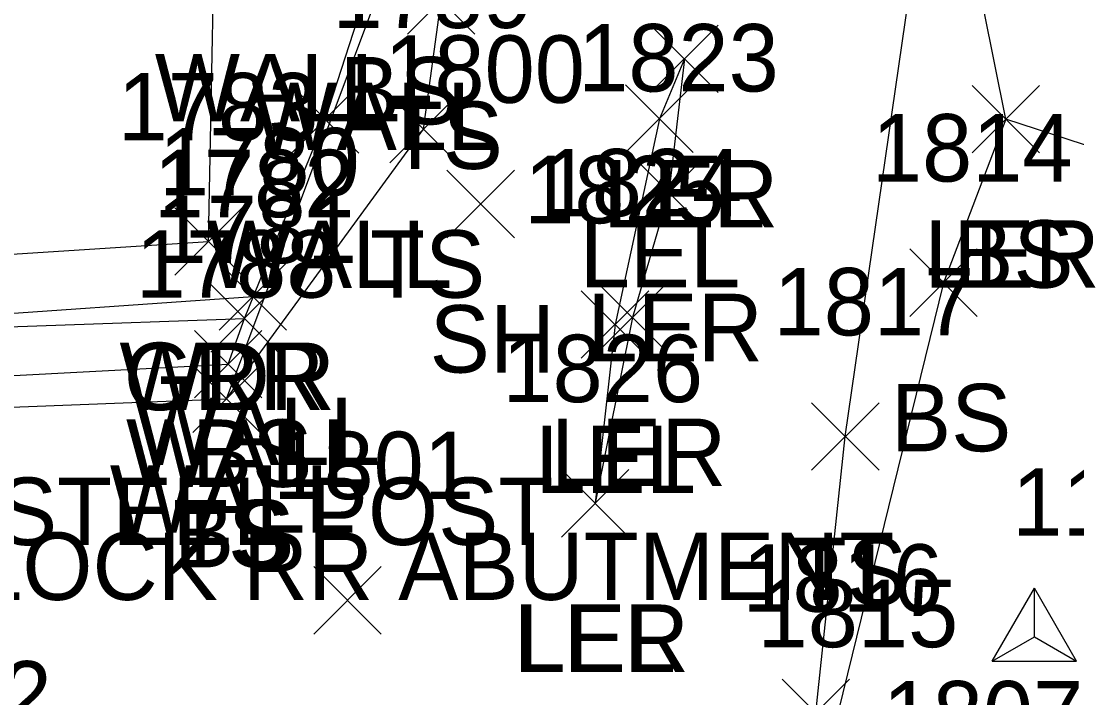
# Model space of a CAD drawing. Extents: x 1638344 to 1639591, y 610835 to 612202.
# Drawn here: x 1638637.19 to 1638668.48, y 611653.56 to 611673.63 of the extents above; entities that cross this region are included whole.
import ezdxf

# ---------------------------------------------------------------- set-up
doc = ezdxf.new("R2010")
doc.units = 0
for name, color, linetype in [('C_I', 7, 'Continuous'), ('CPSM', 7, 'Continuous'), ('L_A', 7, 'Continuous'), ('L_C', 7, 'Continuous'), ('L_I', 7, 'Continuous'), ('L_TIC', 7, 'Continuous'), ('LARO', 7, 'Continuous'), ('LAWA', 7, 'Continuous'), ('LELB', 7, 'Continuous'), ('LW', 7, 'Continuous'), ('R_A', 7, 'Continuous'), ('R_C', 7, 'Continuous'), ('R_I', 7, 'Continuous'), ('R_TIC', 7, 'Continuous'), ('RGR', 7, 'Continuous')]:
    doc.layers.add(name, color=color, linetype=linetype)

msp = doc.modelspace()

# ---------------------------------------------------------------- linework, layer by layer
at = {"layer": 'CPSM'}
for p, q in [((1638665.976, 611654.641), (1638667.226, 611656.806)), ((1638668.476, 611654.641), (1638667.226, 611656.806)), ((1638667.226, 611655.363), (1638667.226, 611656.806)), ((1638665.976, 611654.641), (1638667.226, 611655.363)), ((1638667.226, 611655.363), (1638667.226, 611655.363)), ((1638667.226, 611655.363), (1638668.476, 611654.641)), ((1638665.976, 611654.641), (1638668.476, 611654.641))]:
    msp.add_line(p, q, dxfattribs=at)
at = {"layer": 'L_TIC'}
for points in [[(1638648.64, 611673.242), (1638650.64, 611675.242)], [(1638650.64, 611673.242), (1638648.64, 611675.242)], [(1638655.848, 611671.507), (1638657.848, 611673.507)], [(1638657.848, 611671.507), (1638655.848, 611673.507)], [(1638655.848, 611671.507), (1638657.848, 611673.507)], [(1638657.848, 611671.507), (1638655.848, 611673.507)], [(1638655.107, 611669.733), (1638657.107, 611671.733)], [(1638657.107, 611669.733), (1638655.107, 611671.733)], [(1638665.378, 611669.719), (1638667.378, 611671.719)], [(1638667.378, 611669.719), (1638665.378, 611671.719)], [(1638665.378, 611669.719), (1638667.378, 611671.719)], [(1638667.378, 611669.719), (1638665.378, 611671.719)], [(1638645.203, 611669.713), (1638647.203, 611671.713)], [(1638647.203, 611669.713), (1638645.203, 611671.713)], [(1638648.116, 611669.423), (1638650.116, 611671.423)], [(1638650.116, 611669.423), (1638648.116, 611671.423)], [(1638655.391, 611667.54), (1638657.391, 611669.54)], [(1638657.391, 611667.54), (1638655.391, 611669.54)], [(1638649.809, 611667.203), (1638651.809, 611669.203)], [(1638651.809, 611667.203), (1638649.809, 611669.203)], [(1638641.742, 611666.089), (1638643.742, 611668.089)], [(1638643.742, 611666.089), (1638641.742, 611668.089)], [(1638663.532, 611664.869), (1638665.532, 611666.869)], [(1638665.532, 611664.869), (1638663.532, 611666.869)], [(1638643.053, 611664.46), (1638645.053, 611666.46)], [(1638645.053, 611664.46), (1638643.053, 611666.46)], [(1638642.81, 611663.812), (1638644.81, 611665.812)], [(1638644.81, 611663.812), (1638642.81, 611665.812)], [(1638642.81, 611663.812), (1638644.81, 611665.812)], [(1638644.81, 611663.812), (1638642.81, 611665.812)], [(1638654.307, 611663.835), (1638656.307, 611665.835)], [(1638656.307, 611663.835), (1638654.307, 611665.835)], [(1638653.792, 611663.632), (1638655.792, 611665.632)], [(1638655.792, 611663.632), (1638653.792, 611665.632)], [(1638642.327, 611662.451), (1638644.327, 611664.451)], [(1638644.327, 611662.451), (1638642.327, 611664.451)], [(1638642.277, 611661.426), (1638644.277, 611663.426)], [(1638644.277, 611661.426), (1638642.277, 611663.426)], [(1638642.277, 611661.426), (1638644.277, 611663.426)], [(1638644.277, 611661.426), (1638642.277, 611663.426)], [(1638660.619, 611660.306), (1638662.619, 611662.306)], [(1638662.619, 611660.306), (1638660.619, 611662.306)], [(1638653.201, 611658.326), (1638655.201, 611660.326)], [(1638655.201, 611658.326), (1638653.201, 611660.326)], [(1638653.201, 611658.326), (1638655.201, 611660.326)], [(1638655.201, 611658.326), (1638653.201, 611660.326)], [(1638645.864, 611655.45), (1638647.864, 611657.45)], [(1638647.864, 611655.45), (1638645.864, 611657.45)], [(1638659.747, 611652.111), (1638661.747, 611654.111)], [(1638661.747, 611652.111), (1638659.747, 611654.111)]]:
    msp.add_lwpolyline(points, dxfattribs=at)
at = {"layer": 'LARO'}
for points in [[(1638677.874, 611655.022), (1638679.486, 611663.994), (1638679.763, 611666.345), (1638666.378, 611670.719), (1638664.402, 611680.56), (1638659.089, 611680.603), (1638655.538, 611679.933), (1638651.379, 611684.077), (1638658.688, 611689.813), (1638660.426, 611695.236), (1638662.023, 611697.78), (1638662.102, 611697.781), (1638663.175, 611700.857), (1638663.547, 611703.961), (1638663.377, 611706.584), (1638663.624, 611711.768), (1638664.209, 611717.521), (1638664.377, 611721.2), (1638663.653, 611727.717), (1638657.167, 611737.126)], [(1638656.848, 611672.507), (1638656.391, 611668.54), (1638655.307, 611664.835), (1638654.201, 611659.326)], [(1638656.848, 611672.507), (1638656.107, 611670.733), (1638654.792, 611664.632), (1638654.201, 611659.326)]]:
    msp.add_lwpolyline(points, dxfattribs=at)
at = {"layer": 'LAWA'}
msp.add_lwpolyline([(1638355.934, 611578.146), (1638379.624, 611581.437), (1638409.495, 611585.936), (1638444.058, 611588.569), (1638475.657, 611594.367), (1638498.86, 611601.357), (1638508.245, 611607.886), (1638527.028, 611617.214), (1638546.505, 611624.113), (1638573.22, 611641.376), (1638594.595, 611652.363), (1638613.43, 611662.838), (1638623.727, 611665.865), (1638642.742, 611667.089)], dxfattribs=at)
at = {"layer": 'LELB'}
for points in [[(1638660.747, 611653.111), (1638661.619, 611661.306), (1638664.402, 611680.56)], [(1638643.277, 611662.426), (1638649.116, 611670.423), (1638649.64, 611674.242), (1638650.346, 611680.423)], [(1638628.21, 611661.846), (1638643.277, 611662.426), (1638648.183, 611675.565)], [(1638666.378, 611670.719), (1638664.532, 611665.869), (1638661.143, 611652.058)], [(1638625.327, 611664.153), (1638643.81, 611664.812)]]:
    msp.add_lwpolyline(points, dxfattribs=at)
at = {"layer": 'LW'}
for points in [[(1638628.179, 611662.649), (1638643.327, 611663.451), (1638643.81, 611664.812), (1638646.203, 611670.713), (1638647.529, 611674.805), (1638644.662, 611675.65)], [(1638625.327, 611664.153), (1638644.053, 611665.46)]]:
    msp.add_lwpolyline(points, dxfattribs=at)
at = {"layer": 'R_TIC'}
for points in [[(1638641.742, 611666.089), (1638643.742, 611668.089)], [(1638643.742, 611666.089), (1638641.742, 611668.089)]]:
    msp.add_lwpolyline(points, dxfattribs=at)
at = {"layer": 'RGR'}
msp.add_lwpolyline([(1638642.742, 611667.089), (1638642.991, 611679.673)], dxfattribs=at)

# ---------------------------------------------------------------- texts
at = {"layer": 'C_I'}
msp.add_text('111', height=2, dxfattribs=at).set_placement((1638666.565, 611658.363))
at = {"layer": 'L_A'}
for s, p in [('WALL', (1638641.15, 611670.65)), ('BS', (1638646.624, 611670.565)), ('WALL', (1638644.017, 611669.805)), ('TS', (1638648.05, 611669.242)), ('LER', (1638654.43, 611667.507)), ('LEL', (1638654.485, 611667.507)), ('WALL', (1638642.691, 611665.713)), ('LEL', (1638653.745, 611665.733)), ('LER', (1638663.961, 611665.719)), ('BS', (1638664.819, 611665.719)), ('TS', (1638647.526, 611665.423)), ('LER', (1638653.973, 611663.54)), ('SH', (1638649.297, 611663.203)), ('WDR', (1638640.104, 611662.089)), ('BS', (1638662.973, 611660.869)), ('WALL', (1638640.541, 611660.46)), ('WALL', (1638640.298, 611659.812)), ('BS', (1638642.251, 611659.812)), ('LER', (1638652.89, 611659.835)), ('LEL', (1638652.43, 611659.632)), ('WALL', (1638639.816, 611658.451)), ('TS', (1638641.686, 611657.426)), ('BS', (1638641.718, 611657.426)), ('TS', (1638660.028, 611656.306)), ('LER', (1638651.783, 611654.326)), ('LEL', (1638651.839, 611654.326))]:
    msp.add_text(s, height=2, dxfattribs=at).set_placement(p)
at = {"layer": 'L_C'}
msp.add_text('GRANITE BLOCK RR ABUTMENT', height=2, dxfattribs=at).set_placement((1638621.321, 611656.46))
at = {"layer": 'L_I'}
for s, p in [('1789', (1638646.415, 611673.423)), ('1823', (1638653.698, 611671.54)), ('1800', (1638647.951, 611671.203)), ('1783', (1638640.049, 611670.089)), ('1814', (1638662.406, 611668.869)), ('1780', (1638641.274, 611668.46)), ('1782', (1638641.117, 611667.812)), ('1782', (1638641.117, 611667.812)), ('1824', (1638652.614, 611667.835)), ('1825', (1638652.099, 611667.632)), ('1781', (1638641.201, 611666.451)), ('1788', (1638640.584, 611665.426)), ('1788', (1638640.584, 611665.426)), ('1817', (1638659.493, 611664.306)), ('1826', (1638651.453, 611662.326)), ('1826', (1638651.453, 611662.326)), ('1801', (1638644.66, 611659.45)), ('1816', (1638658.566, 611656.111)), ('1815', (1638659.017, 611655.058)), ('1802', (1638632.147, 611652.646)), ('1807', (1638662.725, 611652.056))]:
    msp.add_text(s, height=2, dxfattribs=at).set_placement(p)
at = {"layer": 'R_A'}
msp.add_text('GRR', height=2, dxfattribs=at).set_placement((1638640.23, 611662.089))
at = {"layer": 'R_C'}
msp.add_text('SGR STEEL POST', height=2, dxfattribs=at).set_placement((1638629.931, 611658.089))
at = {"layer": 'R_I'}
msp.add_text('1783', height=2, dxfattribs=at).set_placement((1638640.049, 611670.089))

doc.saveas('drawing.dxf')
